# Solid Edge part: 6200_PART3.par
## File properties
Author: PARTuser1
Template: Normal.par
Last saved by: Francesco
Revision: 3
Application: Solid Edge
Material: Acciaio
Stile della faccia: Acciaio
Stile di riempimento: ANSI32(Acciaio)
Stile virtuale: Acciaio lavorato a macchina
Coef. of Thermal Exp: 0.0
Thermal Conductivity: 32.0
Specific Heat: 481.0
Modulus of Elasticity: 199947953000.0
Poisson's Ratio: 0.29
Yield Stress: 262000766.0
Ultimate Stress: 358527364.0
Elongation: 0.0
Tipo di contenuto documento: 0
Density: 7833,000 kg/m^3
Accuracy: 0,990
CADENASNORM: 6200_PART3
CADENAS_NB: 6200_PART3
CADENAS_NN: _PART3
CADENAS_NBSYN: 6200_PART3
CADENAS_LINA: 6200_PART3
CADENAS_Z: 8.000
CADENAS_Y0W2: 9.239
CADENAS_R0N1: 0.000
CADENAS_DOUT: 30.000
CADENAS_YI: 8.500
CADENAS_D1ICOS: 23.200
CADENAS_YE: 11.600
CADENAS_Y0I: 10.000
CADENAS_D2: 24.800
CADENAS_D1: 23.200
CADENAS_Y0E: 10.000
CADENAS_X0I: 4.500
CADENAS_BN1: 0.000
CADENAS_CE: 0.000
CADENAS_R2I: 0.200
CADENAS_RWB: 2.381
CADENAS_X0E: 4.500
CADENAS_R2E: 0.200
CADENAS_Z0W2: 3.827
CADENAS_RI: 2.381
CADENAS_X0WB: 4.500
CADENAS_BICOS: 0.000
CADENAS_HIS1: 0.000
CADENAS_RE: 2.381
CADENAS_XI: 0.000
CADENAS_RC: 0.000
CADENAS_XE: 0.000
CADENAS_HE2: 2.600
CADENAS_X0W2: 4.500
CADENAS_BOREDIAMETER: 10.000
CADENAS_RSG: 0.283
CADENAS_BI: 9.000
CADENAS_HN1: 0.000
CADENAS_HI: 3.500
CADENAS_BE: 9.000
CADENAS_R1I: 0.600
CADENAS_HH: 0.000
CADENAS_PRODUCTID: 1050010200.000
CADENAS_HE: 3.400
CADENAS_BEARINGWIDTH: 9.000
CADENAS_R1E: 0.600
CADENAS_BICOS1: 0.000
CADENAS_HICOS: 0.000
CADENAS_DKI: 17.000
CADENAS_Y0WB: 10.000
CADENAS_comment: design:dgbb1; version:5000.3; lang:it; selectedUnitParts:000000; action:download; skf2d3daction.jsp version:2008-03-06; getRequestURI:/skf/skf3dnew/skf2d3daction.jsp
CADENAS_KT: DUMMY
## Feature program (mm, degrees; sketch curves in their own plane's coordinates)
sketch for "unnamed RevolvedProtrusion 1" plane through (0, 0, 0) normal (0, 0, 1) x-axis (1, 0, 0)
  arc centre (4.5, 10) radius 2.381 from (2.119, 10) to (6.881, 10) cw
  line (6.881, 10) -> (2.119, 10)
revolve "unnamed RevolvedProtrusion 1" add finite 360 deg about sketch line (50, 10) -> (-50, 10)
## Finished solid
Body 1: solid body, 1 face, 0 edges, 0 vertices.
  Faces by surface: sphere 1
Spherical faces by radius (mm): R2.381 x1
